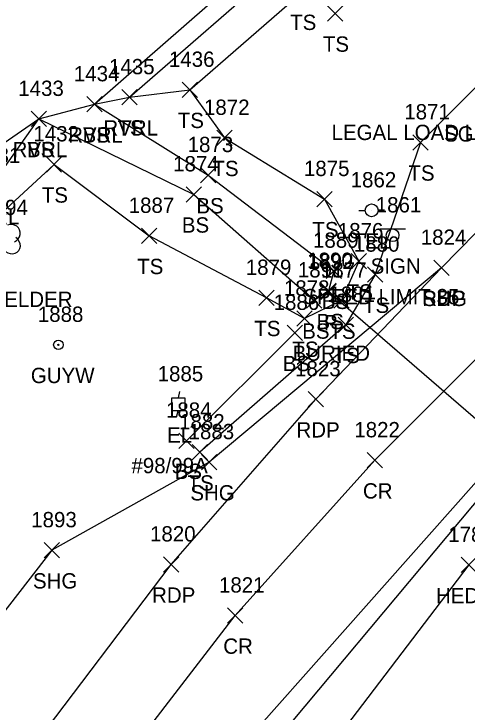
# Model space of a CAD drawing. Extents: x 1600395 to 1603269, y 874955 to 877143.
# Drawn here: x 1601808.1 to 1601867.3, y 875112.5 to 875203.7 of the extents above; entities that cross this region are included whole.
import ezdxf

# ---------------------------------------------------------------- set-up
doc = ezdxf.new("R2010")
doc.units = 0
for name, color, linetype in [('D_A', 7, 'Continuous'), ('D_C', 7, 'Continuous'), ('D_I', 7, 'Continuous'), ('D_TIC', 7, 'Continuous'), ('DCP', 7, 'Continuous'), ('L_A', 7, 'Continuous'), ('L_C', 7, 'Continuous'), ('L_I', 7, 'Continuous'), ('L_TIC', 7, 'Continuous'), ('LAHR', 7, 'Continuous'), ('LAWE', 7, 'Continuous'), ('LELB', 7, 'Continuous'), ('LTD', 7, 'Continuous'), ('P_A', 7, 'Continuous'), ('P_I', 7, 'Continuous'), ('P_TIC', 7, 'Continuous'), ('PET', 7, 'Continuous'), ('PRC', 7, 'Continuous'), ('PSU', 7, 'Continuous'), ('R_C', 7, 'Continuous'), ('S_A', 7, 'Continuous'), ('S_C', 7, 'Continuous'), ('S_I', 7, 'Continuous'), ('SSGN', 7, 'Continuous'), ('U_A', 7, 'Continuous'), ('U_C', 7, 'Continuous'), ('U_I', 7, 'Continuous'), ('UEPT', 7, 'Continuous'), ('UP', 7, 'Continuous'), ('UPGW', 7, 'Continuous')]:
    doc.layers.add(name, color=color, linetype=linetype)

msp = doc.modelspace()

# ---------------------------------------------------------------- linework, layer by layer
at = {"layer": 'D_TIC'}
for points in [[(1601848.192, 875166.377), (1601850.192, 875168.377)], [(1601850.192, 875166.377), (1601848.192, 875168.377)]]:
    msp.add_lwpolyline(points, dxfattribs=at)
at = {"layer": 'DCP'}
msp.add_lwpolyline([(1601876.081, 875144.126), (1601849.192, 875167.377)], dxfattribs=at)
at = {"layer": 'L_TIC'}
for points in [[(1601849.032, 875202.756), (1601851.032, 875204.756)], [(1601851.032, 875202.756), (1601849.032, 875204.756)], [(1601830.09, 875192.783), (1601832.09, 875194.783)], [(1601832.09, 875192.783), (1601830.09, 875194.783)], [(1601830.09, 875192.783), (1601832.09, 875194.783)], [(1601832.09, 875192.783), (1601830.09, 875194.783)], [(1601822.213, 875191.812), (1601824.213, 875193.812)], [(1601824.213, 875191.812), (1601822.213, 875193.812)], [(1601822.213, 875191.812), (1601824.213, 875193.812)], [(1601824.213, 875191.812), (1601822.213, 875193.812)], [(1601817.624, 875190.892), (1601819.624, 875192.892)], [(1601819.624, 875190.892), (1601817.624, 875192.892)], [(1601817.624, 875190.892), (1601819.624, 875192.892)], [(1601819.624, 875190.892), (1601817.624, 875192.892)], [(1601817.624, 875190.892), (1601819.624, 875192.892)], [(1601819.624, 875190.892), (1601817.624, 875192.892)], [(1601810.363, 875188.98), (1601812.363, 875190.98)], [(1601812.363, 875188.98), (1601810.363, 875190.98)], [(1601810.363, 875188.98), (1601812.363, 875190.98)], [(1601812.363, 875188.98), (1601810.363, 875190.98)], [(1601810.363, 875188.98), (1601812.363, 875190.98)], [(1601812.363, 875188.98), (1601810.363, 875190.98)], [(1601834.611, 875186.507), (1601836.611, 875188.507)], [(1601836.611, 875186.507), (1601834.611, 875188.507)], [(1601860.198, 875185.913), (1601862.198, 875187.913)], [(1601862.198, 875185.913), (1601860.198, 875187.913)], [(1601812.338, 875183.041), (1601814.338, 875185.041)], [(1601814.338, 875183.041), (1601812.338, 875185.041)], [(1601812.338, 875183.041), (1601814.338, 875185.041)], [(1601814.338, 875183.041), (1601812.338, 875185.041)], [(1601832.479, 875181.641), (1601834.479, 875183.641)], [(1601834.479, 875181.641), (1601832.479, 875183.641)], [(1601830.589, 875179.122), (1601832.589, 875181.122)], [(1601832.589, 875179.122), (1601830.589, 875181.122)], [(1601847.66, 875178.51), (1601849.66, 875180.51)], [(1601849.66, 875178.51), (1601847.66, 875180.51)], [(1601824.782, 875173.703), (1601826.782, 875175.703)], [(1601826.782, 875173.703), (1601824.782, 875175.703)], [(1601824.782, 875173.703), (1601826.782, 875175.703)], [(1601826.782, 875173.703), (1601824.782, 875175.703)], [(1601852.141, 875170.379), (1601854.141, 875172.379)], [(1601854.141, 875170.379), (1601852.141, 875172.379)], [(1601848.854, 875169.146), (1601850.854, 875171.146)], [(1601850.854, 875169.146), (1601848.854, 875171.146)], [(1601854.268, 875168.635), (1601856.268, 875170.635)], [(1601856.268, 875168.635), (1601854.268, 875170.635)], [(1601848.171, 875166.51), (1601850.171, 875168.51)], [(1601850.171, 875166.51), (1601848.171, 875168.51)], [(1601840.081, 875165.603), (1601842.081, 875167.603)], [(1601842.081, 875165.603), (1601840.081, 875167.603)], [(1601846.303, 875165.266), (1601848.303, 875167.266)], [(1601848.303, 875165.266), (1601846.303, 875167.266)], [(1601846.303, 875165.266), (1601848.303, 875167.266)], [(1601848.303, 875165.266), (1601846.303, 875167.266)], [(1601849.89, 875165.247), (1601851.89, 875167.247)], [(1601851.89, 875165.247), (1601849.89, 875167.247)], [(1601845.048, 875162.89), (1601847.048, 875164.89)], [(1601847.048, 875162.89), (1601845.048, 875164.89)], [(1601850.422, 875162.08), (1601852.422, 875164.08)], [(1601852.422, 875162.08), (1601850.422, 875164.08)], [(1601843.761, 875161.027), (1601845.761, 875163.027)], [(1601845.761, 875161.027), (1601843.761, 875163.027)], [(1601829.648, 875146.942), (1601831.648, 875148.942)], [(1601831.648, 875146.942), (1601829.648, 875148.942)], [(1601831.365, 875145.425), (1601833.365, 875147.425)], [(1601833.365, 875145.425), (1601831.365, 875147.425)], [(1601866.507, 875130.706), (1601868.507, 875132.706)], [(1601868.507, 875130.706), (1601866.507, 875132.706)]]:
    msp.add_lwpolyline(points, dxfattribs=at)
at = {"layer": 'LAHR'}
msp.add_lwpolyline([(1601867.507, 875131.706), (1601841.948, 875098.173), (1601829.33, 875074.095), (1601820.685, 875054.413), (1601829.051, 875051.14)], dxfattribs=at)
at = {"layer": 'LAWE'}
msp.add_lwpolyline([(1601739.843, 875093.177), (1601757.337, 875121.493), (1601768.463, 875137.841), (1601782.196, 875157.26), (1601805.115, 875181.224), (1601811.363, 875189.98), (1601818.624, 875191.892), (1601823.213, 875192.812), (1601844.145, 875211.079), (1601861.587, 875229.673), (1601864.028, 875235.309), (1601870.344, 875255.068), (1601872.905, 875271.961), (1601871.033, 875274.538), (1601876.566, 875297.895), (1601887.708, 875330.048), (1601901.388, 875359.117), (1601917.879, 875393.303), (1601921.976, 875399.296), (1601926.726, 875398.957), (1601927.656, 875400.898), (1601926.508, 875404.409), (1601936.606, 875427.424)], dxfattribs=at)
at = {"layer": 'LELB'}
for points in [[(1602178.369, 875249.145), (1602177.415, 875259.284), (1602168.51, 875260), (1602131.873, 875260.273), (1602108.919, 875258.181), (1602075.252, 875254.524), (1602028.811, 875250.195), (1601991.886, 875244.701), (1601984.631, 875238.194), (1601978.699, 875235.572), (1601960.108, 875224.296), (1601939.912, 875209.734), (1601913.858, 875184.56), (1601890.291, 875159.087), (1601878.527, 875149.192), (1601876.374, 875148.082), (1601869.757, 875141.547), (1601836.036, 875101.247), (1601811.296, 875055.59)], [(1601818.624, 875191.892), (1601842.282, 875212.653), (1601857.679, 875230.343), (1601860.291, 875235.807)], [(1601831.09, 875193.783), (1601845.757, 875206.596), (1601867.259, 875228.25)], [(1601873.59, 875228.471), (1601886.316, 875227.217), (1601889.851, 875219.333), (1601888.826, 875205.111), (1601876.182, 875201.882), (1601861.198, 875186.913), (1601855.268, 875169.635), (1601851.422, 875163.08), (1601832.365, 875146.425)], [(1601823.213, 875192.812), (1601831.09, 875193.783), (1601835.611, 875187.507), (1601848.66, 875179.51), (1601853.141, 875171.379), (1601850.89, 875166.247), (1601846.048, 875163.89), (1601841.081, 875166.603), (1601825.782, 875174.703)], [(1601818.624, 875191.892), (1601833.479, 875182.641), (1601849.854, 875170.146), (1601849.171, 875167.51), (1601847.303, 875166.266)], [(1601727.077, 874960.561), (1601728.142, 874994.468), (1601727.416, 875015.008), (1601727.587, 875043.323), (1601731.608, 875066.074), (1601737.893, 875093.047), (1601755.131, 875122.883), (1601766.475, 875138.812), (1601780.415, 875159.083), (1601801.249, 875183.04), (1601811.363, 875189.98)], [(1601811.363, 875189.98), (1601831.589, 875180.122), (1601847.303, 875166.266)], [(1601745.445, 875091.27), (1601762.135, 875119.29), (1601773.099, 875139.171), (1601782.711, 875155.76), (1601813.338, 875184.041)], [(1601813.338, 875184.041), (1601825.782, 875174.703)], [(1601830.648, 875147.942), (1601844.761, 875162.027)]]:
    msp.add_lwpolyline(points, dxfattribs=at)
at = {"layer": 'LTD'}
for centre, major_axis, ratio in [((1601807.71, 875174.996), (-1.141, -0.483), 0.949671), ((1601807.668, 875173.579), (-1.09, 0.792), 0.841452)]:
    msp.add_ellipse(centre, major_axis=major_axis, ratio=ratio, start_param=1.570796, end_param=4.712389, dxfattribs=at)
at = {"layer": 'P_TIC'}
for points in [[(1601862.919, 875169.533), (1601864.919, 875171.533)], [(1601864.919, 875169.533), (1601862.919, 875171.533)], [(1601862.919, 875169.533), (1601864.919, 875171.533)], [(1601864.919, 875169.533), (1601862.919, 875171.533)], [(1601846.507, 875152.359), (1601848.507, 875154.359)], [(1601848.507, 875152.359), (1601846.507, 875154.359)], [(1601832.603, 875144.136), (1601834.603, 875146.136)], [(1601834.603, 875144.136), (1601832.603, 875146.136)], [(1601854.239, 875144.384), (1601856.239, 875146.384)], [(1601856.239, 875144.384), (1601854.239, 875146.384)], [(1601812.054, 875132.631), (1601814.054, 875134.631)], [(1601814.054, 875132.631), (1601812.054, 875134.631)], [(1601827.654, 875130.775), (1601829.654, 875132.775)], [(1601829.654, 875130.775), (1601827.654, 875132.775)], [(1601836.005, 875124.104), (1601838.005, 875126.104)], [(1601838.005, 875124.104), (1601836.005, 875126.104)]]:
    msp.add_lwpolyline(points, dxfattribs=at)
at = {"layer": 'PET'}
for points in [[(1601981.363, 875249.806), (1601972.89, 875242.44), (1601955.896, 875227.486), (1601938.248, 875211.842), (1601911.531, 875186.457), (1601887.524, 875162.64), (1601873.649, 875148.403), (1601834.558, 875104.332), (1601817.898, 875080.131), (1601806.172, 875058.569), (1601796.417, 875036.344), (1601789.601, 875012.3), (1601785.899, 874989.711)], [(1601764.4, 874992.239), (1601768.772, 875018.84), (1601777.997, 875048.131), (1601790.928, 875076.192), (1601810.073, 875107.229), (1601828.654, 875131.775), (1601847.507, 875153.359), (1601863.919, 875170.533), (1601881.764, 875188.712), (1601893.902, 875201.56), (1601897.71, 875209.517), (1601897.173, 875214.832), (1601896.079, 875222.115), (1601893.32, 875227.875), (1601887.406, 875234.65), (1601882.142, 875236.788)]]:
    msp.add_lwpolyline(points, dxfattribs=at)
at = {"layer": 'PRC'}
msp.add_lwpolyline([(1601775.553, 874992.017), (1601780.37, 875017.597), (1601787.983, 875044.4), (1601800.395, 875072.616), (1601818.138, 875100.611), (1601837.005, 875125.104), (1601855.239, 875145.384), (1601891.245, 875181.434), (1601904.017, 875195.801), (1601914.312, 875205.653), (1601919.011, 875213.201), (1601928.745, 875226.855), (1601931.003, 875235.476), (1601931.432, 875243.625)], dxfattribs=at)
at = {"layer": 'PSU'}
msp.add_lwpolyline([(1601863.919, 875170.533), (1601833.603, 875145.136), (1601813.054, 875133.631), (1601794.635, 875109.895), (1601781.483, 875081.205), (1601775.908, 875056.872), (1601772.452, 875035.366)], dxfattribs=at)
at = {"layer": 'SSGN'}
for p, q in [((1601855.892, 875175.615), (1601859.226, 875175.615)), ((1601857.539, 875174.782), (1601857.539, 875174.782))]:
    msp.add_line(p, q, dxfattribs=at)
msp.add_circle((1601857.539, 875174.782), 0.833, dxfattribs=at)
at = {"layer": 'UEPT'}
for p, q in [((1601829.731, 875154.361), (1601829.565, 875153.528)), ((1601828.731, 875151.861), (1601828.731, 875153.528)), ((1601828.731, 875153.528), (1601830.398, 875153.528)), ((1601830.398, 875153.528), (1601830.398, 875151.861)), ((1601829.565, 875152.694), (1601829.565, 875152.694)), ((1601830.398, 875151.861), (1601828.731, 875151.861)), ((1601829.315, 875151.028), (1601829.565, 875151.861))]:
    msp.add_line(p, q, dxfattribs=at)
at = {"layer": 'UP'}
for p, q in [((1601853.151, 875178.033), (1601853.977, 875178.033)), ((1601854.81, 875178.038), (1601854.81, 875178.038)), ((1601856.477, 875178.038), (1601855.643, 875178.038)), ((1601855.643, 875178.038), (1601855.643, 875178.038)), ((1601856.477, 875178.038), (1601856.477, 875178.038))]:
    msp.add_line(p, q, dxfattribs=at)
msp.add_circle((1601854.81, 875178.038), 0.833, dxfattribs=at)
at = {"layer": 'UPGW'}
for radius in [0.625, 0.0833]:
    msp.add_circle((1601813.919, 875160.466), radius, dxfattribs=at)

# ---------------------------------------------------------------- texts
at = {"layer": 'D_A'}
msp.add_text('P', height=2, dxfattribs=at).set_placement((1601848.57, 875162.377))
at = {"layer": 'D_C'}
msp.add_text('BURIED', height=2, dxfattribs=at).set_placement((1601844.492, 875158.377))
at = {"layer": 'D_I'}
msp.add_text('1892', height=2, dxfattribs=at).set_placement((1601846.5, 875170.377))
at = {"layer": 'L_A'}
for s, p in [('TS', (1601844.167, 875201.596)), ('TS', (1601848.442, 875198.756)), ('TS', (1601829.499, 875188.783)), ('TS', (1601829.499, 875188.783)), ('RVRL', (1601819.78, 875187.812)), ('TS', (1601821.622, 875187.812)), ('RVRL', (1601815.191, 875186.892)), ('BS', (1601817.065, 875186.892)), ('BS', (1601817.065, 875186.892)), ('RVRL', (1601807.93, 875184.98)), ('BS', (1601809.804, 875184.98)), ('BS', (1601809.804, 875184.98)), ('TS', (1601834.02, 875182.507)), ('TS', (1601859.608, 875181.913)), ('TS', (1601811.747, 875179.041)), ('TS', (1601811.747, 875179.041)), ('BS', (1601831.92, 875177.641)), ('RVRL', (1601801.682, 875176.224)), ('BS', (1601830.03, 875175.122)), ('TS', (1601847.07, 875174.51)), ('TS', (1601824.192, 875169.703)), ('TS', (1601824.192, 875169.703)), ('TS', (1601851.55, 875166.379)), ('BS', (1601848.295, 875165.146)), ('TS', (1601853.678, 875164.635)), ('BS', (1601847.612, 875162.51)), ('TS', (1601839.49, 875161.603)), ('BS', (1601845.744, 875161.266)), ('BS', (1601845.744, 875161.266)), ('TS', (1601849.3, 875161.247)), ('TS', (1601844.457, 875158.89)), ('TS', (1601849.831, 875158.08)), ('BS', (1601843.201, 875157.027)), ('BS', (1601829.089, 875142.942)), ('TS', (1601830.774, 875141.425)), ('HEDGE', (1601863.207, 875126.706))]:
    msp.add_text(s, height=2, dxfattribs=at).set_placement(p)
at = {"layer": 'L_C'}
msp.add_text('M. BOXELDER', height=2, dxfattribs=at).set_placement((1601797.479, 875165.412))
at = {"layer": 'L_I'}
for s, p in [('1436', (1601828.342, 875196.783)), ('1436', (1601828.342, 875196.783)), ('1435', (1601820.52, 875195.812)), ('1435', (1601820.52, 875195.812)), ('1434', (1601815.931, 875194.892)), ('1434', (1601815.931, 875194.892)), ('1434', (1601815.931, 875194.892)), ('1433', (1601808.67, 875192.98)), ('1433', (1601808.67, 875192.98)), ('1433', (1601808.67, 875192.98)), ('1872', (1601832.918, 875190.507)), ('1871', (1601859.072, 875189.913)), ('1432', (1601810.645, 875187.041)), ('1432', (1601810.645, 875187.041)), ('1873', (1601830.786, 875185.641)), ('1431', (1601802.989, 875184.224)), ('1874', (1601828.896, 875183.122)), ('1875', (1601845.968, 875182.51)), ('1887', (1601823.089, 875177.703)), ('1887', (1601823.089, 875177.703)), ('1894', (1601803.975, 875177.412)), ('1876', (1601850.393, 875174.379)), ('1889', (1601847.153, 875173.146)), ('1880', (1601852.489, 875172.635)), ('1890', (1601846.391, 875170.51)), ('1879', (1601838.38, 875169.603)), ('1891', (1601845.177, 875169.266)), ('1891', (1601845.177, 875169.266)), ('1877', (1601848.198, 875169.247)), ('1878', (1601843.355, 875166.89)), ('1881', (1601849.296, 875166.08)), ('1886', (1601842.013, 875165.027)), ('1884', (1601827.955, 875150.942)), ('1882', (1601829.672, 875149.425)), ('1789', (1601864.806, 875134.706))]:
    msp.add_text(s, height=2, dxfattribs=at).set_placement(p)
at = {"layer": 'P_A'}
for s, p in [('SHG', (1601861.455, 875165.533)), ('RDP', (1601861.407, 875165.533)), ('RDP', (1601844.995, 875148.359)), ('CR', (1601853.672, 875140.384)), ('SHG', (1601831.138, 875140.136)), ('SHG', (1601810.589, 875128.631)), ('RDP', (1601826.142, 875126.775)), ('CR', (1601835.438, 875120.104))]:
    msp.add_text(s, height=2, dxfattribs=at).set_placement(p)
at = {"layer": 'P_I'}
for s, p in [('1824', (1601861.226, 875173.533)), ('1824', (1601861.226, 875173.533)), ('1823', (1601844.814, 875156.359)), ('1822', (1601852.546, 875148.384)), ('1883', (1601830.91, 875148.136)), ('1893', (1601810.361, 875136.631)), ('1820', (1601825.874, 875134.775)), ('1821', (1601834.879, 875128.104))]:
    msp.add_text(s, height=2, dxfattribs=at).set_placement(p)
at = {"layer": 'R_C'}
msp.add_text('SGR W/STEEL POSTS', height=2, dxfattribs=at).set_placement((1601864.269, 875187.015))
at = {"layer": 'S_A'}
msp.add_text('SIGN', height=2, dxfattribs=at).set_placement((1601854.677, 875169.761))
at = {"layer": 'S_C'}
for s, p in [('LEGAL LOAD LIMIT 24000 POUNDS', (1601849.572, 875187.22)), ('SPEED LIMIT 35', (1601845.898, 875165.761))]:
    msp.add_text(s, height=2, dxfattribs=at).set_placement(p)
at = {"layer": 'S_I'}
msp.add_text('1861', height=2, dxfattribs=at).set_placement((1601855.346, 875177.761))
at = {"layer": 'U_A'}
for s, p in [('TEL', (1601852.369, 875173.038)), ('GUYW', (1601810.313, 875155.466)), ('EL', (1601828.1, 875147.694))]:
    msp.add_text(s, height=2, dxfattribs=at).set_placement(p)
at = {"layer": 'U_C'}
msp.add_text('#98/99A', height=2, dxfattribs=at).set_placement((1601823.447, 875143.694))
at = {"layer": 'U_I'}
for s, p in [('1862', (1601852.07, 875181.038)), ('1888', (1601811.226, 875163.466)), ('1885', (1601826.872, 875155.694))]:
    msp.add_text(s, height=2, dxfattribs=at).set_placement(p)

doc.saveas('drawing.dxf')
